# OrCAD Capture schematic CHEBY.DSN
size A
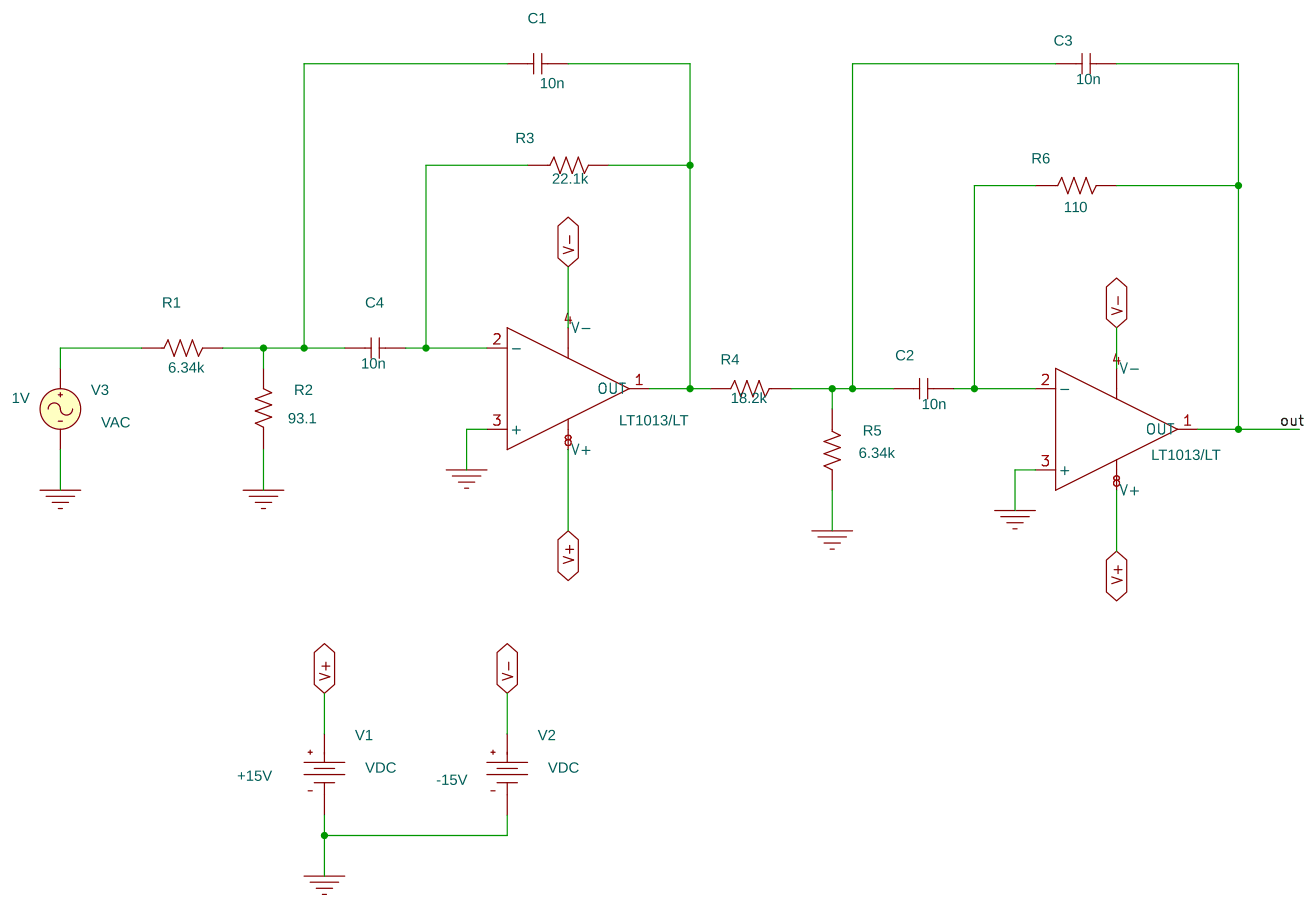
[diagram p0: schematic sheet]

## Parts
C1  10n
C2  10n
C3  10n
C4  10n
R1  6.34k
R2  93.1
R3  22.1k
R4  18.2k
R5  6.34k
R6  110
U1  LT1013/LT  [DIP.100/8/W.300/L.425]  (section A)
U2  LT1013/LT  [DIP.100/8/W.300/L.425]  (section A)
V1  VDC
V2  VDC
V3  VAC

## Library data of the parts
C1-C4 = Cbreak
R1-R6 = Rbreak
U1 U2 = LT1013_LT
V1 = VDC: DC: +15V
V2 = VDC: DC: -15V
V3 = VAC: ACMAG: 1V

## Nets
0: R2.1 R5.0(2) U1.3(+) U2.3(+) V1.1(-) V2.1(-) V3.2(-)
out: C3.1(2) R6.0(2) U2.1(OUT)
V+: U1.8(V+) U2.8(V+) V1.0(+)
V-: U1.4(V-) U2.4(V-) V2.0(+)
N00104: R1.1 V3.1(+)
N00111: C1.0(1) C4.0(1) R1.0(2) R2.0(2)
N00147: C2.0(1) C3.0(1) R4.1 R5.1
N00162: C2.1(2) R6.1 U2.2(-)
N00236: C4.1(2) R3.1 U1.2(-)
N00527: C1.1(2) R3.0(2) R4.0(2) U1.1(OUT)
